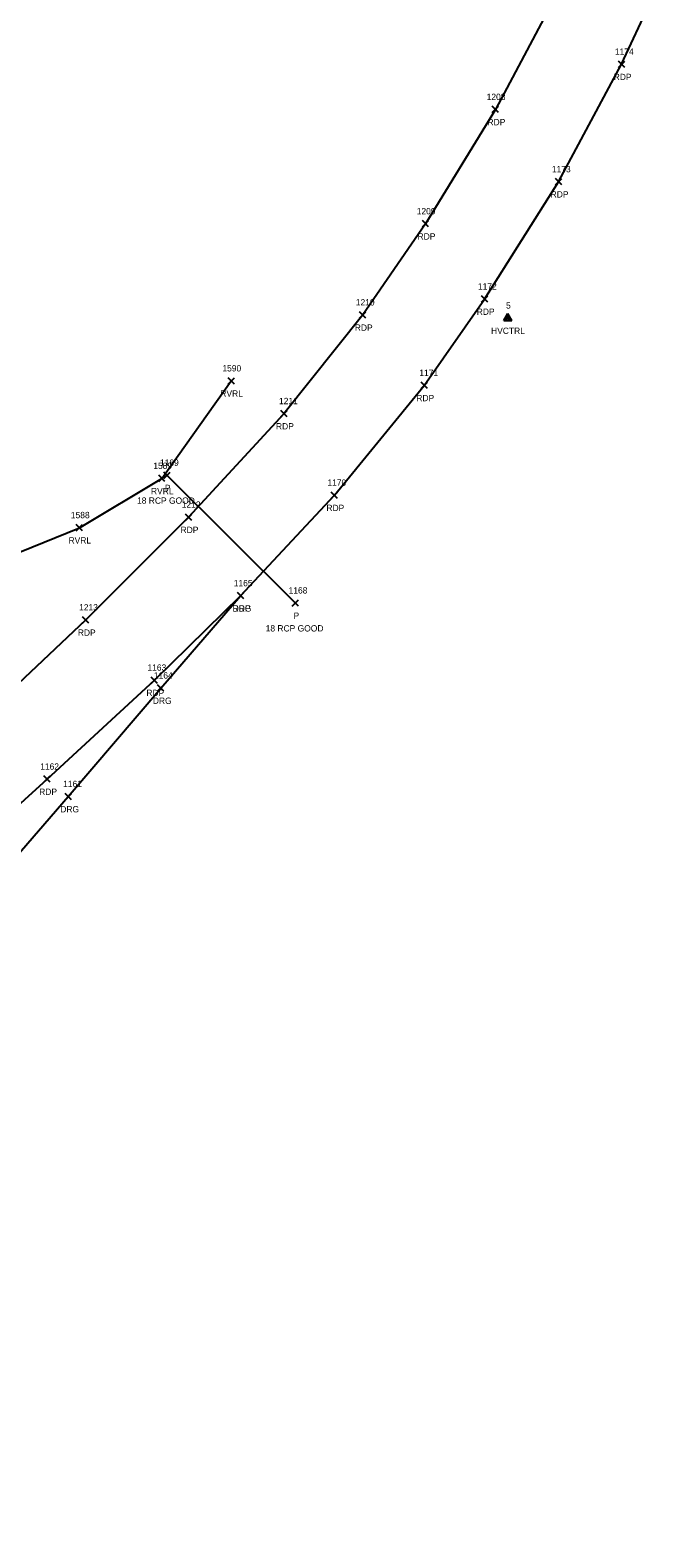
# Model space of a CAD drawing. Extents: x 1496556 to 1498241, y 599216 to 604470.
# Drawn here: x 1497837.4 to 1498039.7, y 603254 to 603730.8 of the extents above; entities that cross this region are included whole.
import ezdxf

# ---------------------------------------------------------------- set-up
doc = ezdxf.new("R2010")
doc.units = 0
for name, color, linetype in [('C_A', 7, 'Continuous'), ('C_I', 7, 'Continuous'), ('CPSM', 7, 'Continuous'), ('D_A', 7, 'Continuous'), ('D_C', 7, 'Continuous'), ('D_I', 7, 'Continuous'), ('D_TIC', 7, 'Continuous'), ('DCP', 7, 'Continuous'), ('L_A', 7, 'Continuous'), ('L_I', 7, 'Continuous'), ('L_TIC', 7, 'Continuous'), ('LAWE', 7, 'Continuous'), ('P_A', 7, 'Continuous'), ('P_I', 7, 'Continuous'), ('P_TIC', 7, 'Continuous'), ('PET', 7, 'Continuous'), ('R_A', 7, 'Continuous'), ('R_I', 7, 'Continuous'), ('R_TIC', 7, 'Continuous'), ('RDG', 7, 'Continuous')]:
    doc.layers.add(name, color=color, linetype=linetype)

msp = doc.modelspace()

# ---------------------------------------------------------------- linework, layer by layer
at = {"layer": 'CPSM'}
for p, q in [((1497987.24, 603639.01), (1497988.49, 603641.18)), ((1497987.24, 603639.01), (1497988.49, 603639.74)), ((1497987.24, 603639.01), (1497989.74, 603639.01)), ((1497989.74, 603639.01), (1497988.49, 603641.18)), ((1497988.49, 603639.74), (1497988.49, 603641.18)), ((1497988.49, 603639.74), (1497988.49, 603639.74)), ((1497988.49, 603639.74), (1497989.74, 603639.01))]:
    msp.add_line(p, q, dxfattribs=at)
at = {"layer": 'D_TIC'}
for points in [[(1497879.63, 603589.03), (1497881.63, 603591.03)], [(1497881.63, 603589.03), (1497879.63, 603591.03)], [(1497920.31, 603548.64), (1497922.31, 603550.64)], [(1497922.31, 603548.64), (1497920.31, 603550.64)]]:
    msp.add_lwpolyline(points, dxfattribs=at)
at = {"layer": 'DCP'}
msp.add_lwpolyline([(1497921.31, 603549.64), (1497880.63, 603590.03)], dxfattribs=at)
at = {"layer": 'L_TIC'}
for points in [[(1497899.98, 603618.87), (1497901.98, 603620.87)], [(1497901.98, 603618.87), (1497899.98, 603620.87)], [(1497878.04, 603588.04), (1497880.04, 603590.04)], [(1497880.04, 603588.04), (1497878.04, 603590.04)], [(1497851.95, 603572.46), (1497853.95, 603574.46)], [(1497853.95, 603572.46), (1497851.95, 603574.46)]]:
    msp.add_lwpolyline(points, dxfattribs=at)
at = {"layer": 'LAWE'}
msp.add_lwpolyline([(1497519.31, 603418.69), (1497550.81, 603423.71), (1497584.3, 603433.63), (1497606.43, 603447.91), (1497635.34, 603468.46), (1497688.56, 603489.19), (1497749.06, 603518.5), (1497781.95, 603538.62), (1497814.89, 603558.06), (1497852.95, 603573.46), (1497879.04, 603589.04), (1497900.98, 603619.87)], dxfattribs=at)
at = {"layer": 'P_TIC'}
for points in [[(1498023.5, 603719), (1498025.5, 603721)], [(1498025.5, 603719), (1498023.5, 603721)], [(1497983.58, 603704.71), (1497985.58, 603706.71)], [(1497985.58, 603704.71), (1497983.58, 603706.71)], [(1498003.55, 603681.86), (1498005.55, 603683.86)], [(1498005.55, 603681.86), (1498003.55, 603683.86)], [(1497961.45, 603668.56), (1497963.45, 603670.56)], [(1497963.45, 603668.56), (1497961.45, 603670.56)], [(1497980.16, 603644.77), (1497982.16, 603646.77)], [(1497982.16, 603644.77), (1497980.16, 603646.77)], [(1497941.61, 603639.73), (1497943.61, 603641.73)], [(1497943.61, 603639.73), (1497941.61, 603641.73)], [(1497961.05, 603617.46), (1497963.05, 603619.46)], [(1497963.05, 603617.46), (1497961.05, 603619.46)], [(1497916.66, 603608.52), (1497918.66, 603610.52)], [(1497918.66, 603608.52), (1497916.66, 603610.52)], [(1497932.62, 603582.71), (1497934.62, 603584.71)], [(1497934.62, 603582.71), (1497932.62, 603584.71)], [(1497886.48, 603575.77), (1497888.48, 603577.77)], [(1497888.48, 603575.77), (1497886.48, 603577.77)], [(1497902.96, 603550.93), (1497904.96, 603552.93)], [(1497904.96, 603550.93), (1497902.96, 603552.93)], [(1497853.98, 603543.28), (1497855.98, 603545.28)], [(1497855.98, 603543.28), (1497853.98, 603545.28)], [(1497875.67, 603524.23), (1497877.67, 603526.23)], [(1497877.67, 603524.23), (1497875.67, 603526.23)], [(1497841.75, 603492.95), (1497843.75, 603494.95)], [(1497843.75, 603492.95), (1497841.75, 603494.95)]]:
    msp.add_lwpolyline(points, dxfattribs=at)
at = {"layer": 'PET'}
for points in [[(1497522.29, 603204.31), (1497552.95, 603231.97), (1497591.08, 603266.91), (1497627.26, 603299.53), (1497662.95, 603331.45), (1497697.84, 603363.51), (1497746.34, 603407.32), (1497759.4, 603419.2), (1497780.77, 603438.17), (1497814.38, 603468.18), (1497842.75, 603493.95), (1497876.67, 603525.23), (1497903.96, 603551.93), (1497933.62, 603583.71), (1497962.05, 603618.46), (1497981.16, 603645.77), (1498004.55, 603682.86), (1498024.5, 603720), (1498039.75, 603752.79)], [(1498003.54, 603741.59), (1497984.58, 603705.71), (1497962.45, 603669.56), (1497942.61, 603640.73), (1497917.66, 603609.52), (1497887.48, 603576.77), (1497854.98, 603544.28), (1497821.8, 603513.04), (1497792.69, 603486.99), (1497765.2, 603461.99), (1497728.75, 603428.73), (1497692.32, 603395.47), (1497651.92, 603358.61), (1497618.31, 603327.9), (1497580.33, 603293.36), (1497544.07, 603260.5)]]:
    msp.add_lwpolyline(points, dxfattribs=at)
at = {"layer": 'R_TIC'}
for points in [[(1497902.96, 603550.93), (1497904.96, 603552.93)], [(1497904.96, 603550.93), (1497902.96, 603552.93)], [(1497877.7, 603521.75), (1497879.7, 603523.75)], [(1497879.7, 603521.75), (1497877.7, 603523.75)], [(1497848.43, 603487.43), (1497850.43, 603489.43)], [(1497850.43, 603487.43), (1497848.43, 603489.43)]]:
    msp.add_lwpolyline(points, dxfattribs=at)
at = {"layer": 'RDG'}
msp.add_lwpolyline([(1497759.4, 603419.2), (1497784.91, 603433.8), (1497823.17, 603458.16), (1497849.43, 603488.43), (1497878.7, 603522.75), (1497903.96, 603551.93)], dxfattribs=at)

# ---------------------------------------------------------------- texts
at = {"layer": 'C_A'}
msp.add_text('HVCTRL', height=2, dxfattribs=at).set_placement((1497983.19, 603634.74))
at = {"layer": 'C_I'}
msp.add_text('5', height=2, dxfattribs=at).set_placement((1497987.93, 603642.74))
at = {"layer": 'D_A'}
for p in [(1497880.01, 603585.03), (1497920.69, 603544.64)]:
    msp.add_text('P', height=2, dxfattribs=at).set_placement(p)
at = {"layer": 'D_C'}
for p in [(1497871.2, 603581.03), (1497911.89, 603540.64)]:
    msp.add_text('18 RCP GOOD', height=2, dxfattribs=at).set_placement(p)
at = {"layer": 'D_I'}
for s, p in [('1169', (1497878.45, 603593.03)), ('1168', (1497919.14, 603552.64))]:
    msp.add_text(s, height=2, dxfattribs=at).set_placement(p)
at = {"layer": 'L_A'}
for p in [(1497897.55, 603614.87), (1497875.61, 603584.04), (1497849.52, 603568.46)]:
    msp.add_text('RVRL', height=2, dxfattribs=at).set_placement(p)
at = {"layer": 'L_I'}
for s, p in [('1590', (1497898.2, 603622.87)), ('1589', (1497876.34, 603592.04)), ('1588', (1497850.26, 603576.46))]:
    msp.add_text(s, height=2, dxfattribs=at).set_placement(p)
at = {"layer": 'P_A'}
for p in [(1498021.99, 603715), (1497982.06, 603700.71), (1498002.04, 603677.86), (1497959.94, 603664.56), (1497978.65, 603640.77), (1497940.09, 603635.73), (1497959.54, 603613.46), (1497915.15, 603604.52), (1497931.11, 603578.71), (1497884.97, 603571.77), (1497901.45, 603546.93), (1497852.47, 603539.28), (1497874.15, 603520.23), (1497840.24, 603488.95)]:
    msp.add_text('RDP', height=2, dxfattribs=at).set_placement(p)
at = {"layer": 'P_I'}
for s, p in [('1174', (1498022.37, 603723)), ('1208', (1497981.8, 603708.71)), ('1173', (1498002.43, 603685.86)), ('1209', (1497959.67, 603672.56)), ('1172', (1497979.04, 603648.77)), ('1210', (1497940.39, 603643.73)), ('1171', (1497960.49, 603621.46)), ('1211', (1497916.1, 603612.52)), ('1170', (1497931.41, 603586.71)), ('1212', (1497885.35, 603579.77)), ('1165', (1497901.79, 603554.93)), ('1213', (1497852.86, 603547.28)), ('1163', (1497874.49, 603528.23)), ('1162', (1497840.57, 603496.95))]:
    msp.add_text(s, height=2, dxfattribs=at).set_placement(p)
at = {"layer": 'R_A'}
for p in [(1497901.45, 603546.93), (1497876.19, 603517.75), (1497846.92, 603483.43)]:
    msp.add_text('DRG', height=2, dxfattribs=at).set_placement(p)
at = {"layer": 'R_I'}
for s, p in [('1165', (1497901.79, 603554.93)), ('1164', (1497876.53, 603525.75)), ('1161', (1497847.82, 603491.43))]:
    msp.add_text(s, height=2, dxfattribs=at).set_placement(p)

doc.saveas('drawing.dxf')
